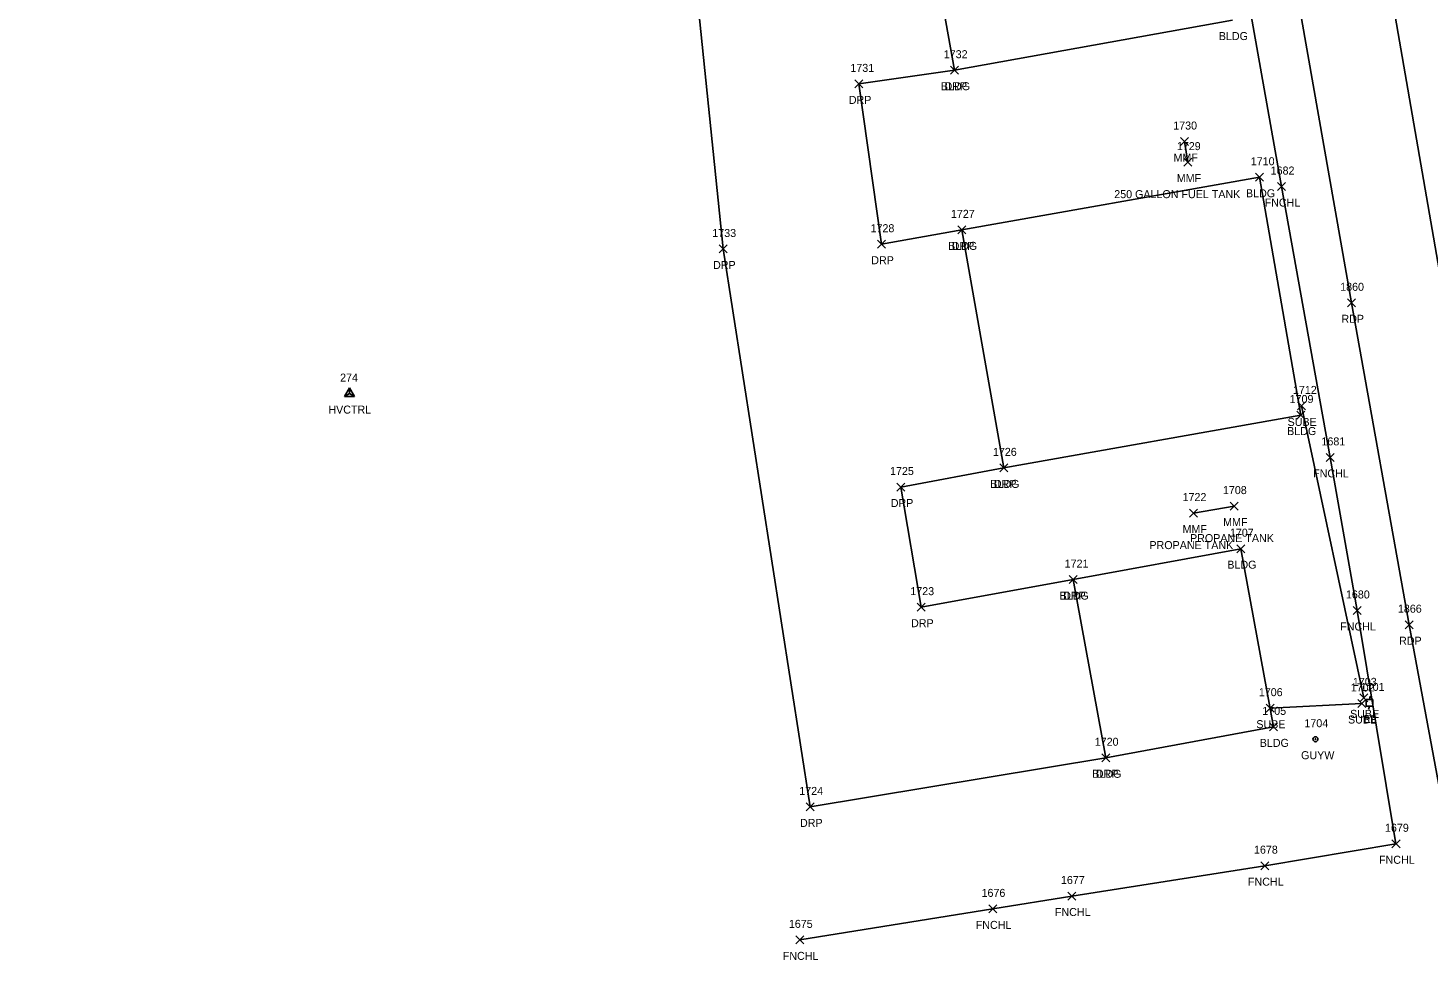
# Model space of a CAD drawing. Extents: x 1481523 to 1489083, y 884156 to 893756.
# Drawn here: x 1486301.2 to 1486651.1, y 888084.1 to 888317 of the extents above; entities that cross this region are included whole.
import ezdxf

# ---------------------------------------------------------------- set-up
doc = ezdxf.new("R2010")
doc.units = 0
for name, color, linetype in [('C_A', 7, 'Continuous'), ('C_I', 7, 'Continuous'), ('CPSM', 7, 'Continuous'), ('L_A', 7, 'Continuous'), ('L_C', 7, 'Continuous'), ('L_I', 7, 'Continuous'), ('L_TIC', 7, 'Continuous'), ('LBC', 7, 'Continuous'), ('LDEFAULT', 7, 'Continuous'), ('LFNC', 7, 'Continuous'), ('P_A', 7, 'Continuous'), ('P_I', 7, 'Continuous'), ('P_TIC', 7, 'Continuous'), ('PET', 7, 'Continuous'), ('R_A', 7, 'Continuous'), ('R_I', 7, 'Continuous'), ('R_TIC', 7, 'Continuous'), ('RDP', 7, 'Continuous'), ('U_A', 7, 'Continuous'), ('U_I', 7, 'Continuous'), ('U_TIC', 7, 'Continuous'), ('UE', 7, 'Continuous'), ('UEPT', 7, 'Continuous'), ('UPGW', 7, 'Continuous')]:
    doc.layers.add(name, color=color, linetype=linetype)

msp = doc.modelspace()

# ---------------------------------------------------------------- linework, layer by layer
at = {"layer": 'CPSM'}
for p, q in [((1486380.33, 888224.92), (1486381.58, 888227.08)), ((1486382.83, 888224.92), (1486381.58, 888227.08)), ((1486381.58, 888225.64), (1486381.58, 888227.08)), ((1486380.33, 888224.92), (1486381.58, 888225.64)), ((1486380.33, 888224.92), (1486382.83, 888224.92)), ((1486381.58, 888225.64), (1486381.58, 888225.64)), ((1486381.58, 888225.64), (1486382.83, 888224.92))]:
    msp.add_line(p, q, dxfattribs=at)
at = {"layer": 'L_TIC'}
for points in [[(1486531.76, 888305.44), (1486533.76, 888307.44)], [(1486533.76, 888305.44), (1486531.76, 888307.44)], [(1486589.19, 888287.61), (1486591.19, 888289.61)], [(1486591.19, 888287.61), (1486589.19, 888289.61)], [(1486590.02, 888282.47), (1486592.02, 888284.47)], [(1486592.02, 888282.47), (1486590.02, 888284.47)], [(1486608, 888278.69), (1486610, 888280.69)], [(1486610, 888278.69), (1486608, 888280.69)], [(1486613.5, 888276.37), (1486615.5, 888278.37)], [(1486615.5, 888276.37), (1486613.5, 888278.37)], [(1486533.55, 888265.55), (1486535.55, 888267.55)], [(1486535.55, 888265.55), (1486533.55, 888267.55)], [(1486533.55, 888265.55), (1486535.55, 888267.55)], [(1486535.55, 888265.55), (1486533.55, 888267.55)], [(1486618.28, 888219.28), (1486620.28, 888221.28)], [(1486620.28, 888219.28), (1486618.28, 888221.28)], [(1486618.28, 888219.28), (1486620.28, 888221.28)], [(1486620.28, 888219.28), (1486618.28, 888221.28)], [(1486625.62, 888208.7), (1486627.62, 888210.7)], [(1486627.62, 888208.7), (1486625.62, 888210.7)], [(1486544.1, 888206.08), (1486546.1, 888208.08)], [(1486546.1, 888206.08), (1486544.1, 888208.08)], [(1486601.6, 888196.53), (1486603.6, 888198.53)], [(1486603.6, 888196.53), (1486601.6, 888198.53)], [(1486591.45, 888194.79), (1486593.45, 888196.79)], [(1486593.45, 888194.79), (1486591.45, 888196.79)], [(1486603.34, 888185.89), (1486605.34, 888187.89)], [(1486605.34, 888185.89), (1486603.34, 888187.89)], [(1486561.41, 888178.16), (1486563.41, 888180.16)], [(1486563.41, 888178.16), (1486561.41, 888180.16)], [(1486561.41, 888178.16), (1486563.41, 888180.16)], [(1486563.41, 888178.16), (1486561.41, 888180.16)], [(1486632.4, 888170.45), (1486634.4, 888172.45)], [(1486634.4, 888170.45), (1486632.4, 888172.45)], [(1486611.44, 888141.37), (1486613.44, 888143.37)], [(1486613.44, 888141.37), (1486611.44, 888143.37)], [(1486611.44, 888141.37), (1486613.44, 888143.37)], [(1486613.44, 888141.37), (1486611.44, 888143.37)], [(1486569.58, 888133.65), (1486571.58, 888135.65)], [(1486571.58, 888133.65), (1486569.58, 888135.65)], [(1486642.08, 888112.16), (1486644.08, 888114.16)], [(1486644.08, 888112.16), (1486642.08, 888114.16)], [(1486609.33, 888106.69), (1486611.33, 888108.69)], [(1486611.33, 888106.69), (1486609.33, 888108.69)], [(1486561.09, 888099.11), (1486563.09, 888101.11)], [(1486563.09, 888099.11), (1486561.09, 888101.11)], [(1486541.31, 888095.89), (1486543.31, 888097.89)], [(1486543.31, 888095.89), (1486541.31, 888097.89)], [(1486493.1, 888088.15), (1486495.1, 888090.15)], [(1486495.1, 888088.15), (1486493.1, 888090.15)]]:
    msp.add_lwpolyline(points, dxfattribs=at)
at = {"layer": 'LBC'}
for points in [[(1486602.21, 888318.97), (1486532.76, 888306.44), (1486523.87, 888356.26)], [(1486619.28, 888220.28), (1486609, 888279.69), (1486534.55, 888266.55)], [(1486619.28, 888220.28), (1486545.1, 888207.08), (1486534.55, 888266.55)], [(1486612.44, 888142.37), (1486604.34, 888186.89), (1486562.41, 888179.16)], [(1486612.44, 888142.37), (1486570.58, 888134.65), (1486562.41, 888179.16)]]:
    msp.add_lwpolyline(points, dxfattribs=at)
at = {"layer": 'LDEFAULT'}
for points in [[(1486591.02, 888283.47), (1486590.19, 888288.61)], [(1486602.6, 888197.53), (1486592.45, 888195.79)]]:
    msp.add_lwpolyline(points, dxfattribs=at)
at = {"layer": 'LFNC'}
msp.add_lwpolyline([(1486494.1, 888089.15), (1486542.31, 888096.89), (1486562.09, 888100.11), (1486610.33, 888107.69), (1486643.08, 888113.16), (1486633.4, 888171.45), (1486626.62, 888209.7), (1486614.5, 888277.37), (1486602.35, 888345.54), (1486591.72, 888405.11), (1486588.69, 888421.87), (1486578, 888481.54), (1486565.98, 888549.48), (1486554.04, 888616.26), (1486540.66, 888690.96), (1486537.54, 888707.46), (1486527.52, 888764.64), (1486517.54, 888822.03), (1486505.67, 888889.2), (1486493.41, 888956.36), (1486481.11, 889023.64), (1486470.56, 889080.63), (1486461.7, 889127.71), (1486454.26, 889166.3)], dxfattribs=at)
at = {"layer": 'P_TIC'}
for points in [[(1486630.96, 888247.32), (1486632.96, 888249.32)], [(1486632.96, 888247.32), (1486630.96, 888249.32)], [(1486645.36, 888166.9), (1486647.36, 888168.9)], [(1486647.36, 888166.9), (1486645.36, 888168.9)]]:
    msp.add_lwpolyline(points, dxfattribs=at)
at = {"layer": 'PET'}
for points in [[(1486482.46, 889213.8), (1486493.22, 889156.8), (1486512.17, 889057.76), (1486527.58, 888974.51), (1486542.53, 888889.08), (1486553.79, 888825.37), (1486565.07, 888760.91), (1486577.19, 888690.78), (1486591.4, 888610.57), (1486602.78, 888547.25), (1486614.23, 888481.5), (1486627.06, 888409.28), (1486638.94, 888342.58), (1486654.61, 888252.22), (1486669.1, 888181.27), (1486680.17, 888112.03), (1486680.99, 888105.73)], [(1486459.06, 889211.36), (1486470.75, 889147.47), (1486504.42, 888970.47), (1486519.24, 888886.05), (1486530.77, 888821.38), (1486542.03, 888758.69), (1486549.22, 888711.97), (1486553.24, 888690.65), (1486568.55, 888607.7), (1486579.98, 888541.46), (1486590.64, 888481.54), (1486600.71, 888424.31), (1486604.32, 888404.42), (1486616.77, 888334.61), (1486631.96, 888248.32), (1486646.36, 888167.9), (1486656.21, 888114.83)]]:
    msp.add_lwpolyline(points, dxfattribs=at)
at = {"layer": 'R_TIC'}
for points in [[(1486531.76, 888305.44), (1486533.76, 888307.44)], [(1486533.76, 888305.44), (1486531.76, 888307.44)], [(1486507.85, 888302.02), (1486509.85, 888304.02)], [(1486509.85, 888302.02), (1486507.85, 888304.02)], [(1486533.55, 888265.55), (1486535.55, 888267.55)], [(1486535.55, 888265.55), (1486533.55, 888267.55)], [(1486473.92, 888260.77), (1486475.92, 888262.77)], [(1486475.92, 888260.77), (1486473.92, 888262.77)], [(1486513.47, 888261.96), (1486515.47, 888263.96)], [(1486515.47, 888261.96), (1486513.47, 888263.96)], [(1486544.1, 888206.08), (1486546.1, 888208.08)], [(1486546.1, 888206.08), (1486544.1, 888208.08)], [(1486518.34, 888201.3), (1486520.34, 888203.3)], [(1486520.34, 888201.3), (1486518.34, 888203.3)], [(1486561.41, 888178.16), (1486563.41, 888180.16)], [(1486563.41, 888178.16), (1486561.41, 888180.16)], [(1486523.4, 888171.28), (1486525.4, 888173.28)], [(1486525.4, 888171.28), (1486523.4, 888173.28)], [(1486569.58, 888133.65), (1486571.58, 888135.65)], [(1486571.58, 888133.65), (1486569.58, 888135.65)], [(1486495.65, 888121.37), (1486497.65, 888123.37)], [(1486497.65, 888121.37), (1486495.65, 888123.37)]]:
    msp.add_lwpolyline(points, dxfattribs=at)
at = {"layer": 'RDP'}
for points in [[(1486570.58, 888134.65), (1486496.65, 888122.37), (1486474.92, 888261.77), (1486467.85, 888330.77), (1486458.78, 888418.3), (1486415.84, 888670.58), (1486400.74, 888672.5), (1486301.22, 888657.33)], [(1486534.55, 888266.55), (1486514.47, 888262.96), (1486508.85, 888303.02), (1486532.76, 888306.44)], [(1486562.41, 888179.16), (1486524.4, 888172.28), (1486519.34, 888202.3), (1486545.1, 888207.08)]]:
    msp.add_lwpolyline(points, dxfattribs=at)
at = {"layer": 'U_TIC'}
for points in [[(1486618.46, 888221.56), (1486620.46, 888223.56)], [(1486620.46, 888221.56), (1486618.46, 888223.56)], [(1486633.54, 888147.21), (1486635.54, 888149.21)], [(1486635.54, 888147.21), (1486633.54, 888149.21)], [(1486634.07, 888148.62), (1486636.07, 888150.62)], [(1486636.07, 888148.62), (1486634.07, 888150.62)], [(1486610.63, 888146.04), (1486612.63, 888148.04)], [(1486612.63, 888146.04), (1486610.63, 888148.04)]]:
    msp.add_lwpolyline(points, dxfattribs=at)
at = {"layer": 'UE'}
for points in [[(1486635.07, 888149.62), (1486619.46, 888222.56)], [(1486634.54, 888148.21), (1486611.63, 888147.04)]]:
    msp.add_lwpolyline(points, dxfattribs=at)
at = {"layer": 'UEPT'}
for p, q in [((1486635.64, 888147.53), (1486635.64, 888149.19)), ((1486635.64, 888149.19), (1486637.31, 888149.19)), ((1486636.64, 888150.03), (1486636.47, 888149.19)), ((1486637.31, 888149.19), (1486637.31, 888147.53)), ((1486637.31, 888147.53), (1486635.64, 888147.53)), ((1486636.22, 888146.69), (1486636.47, 888147.53)), ((1486636.47, 888148.36), (1486636.47, 888148.36))]:
    msp.add_line(p, q, dxfattribs=at)
at = {"layer": 'UPGW'}
for radius in [0.625, 0.0833]:
    msp.add_circle((1486622.96, 888139.29), radius, dxfattribs=at)

# ---------------------------------------------------------------- texts
at = {"layer": 'C_A'}
msp.add_text('HVCTRL', height=2, dxfattribs=at).set_placement((1486376.28, 888220.64))
at = {"layer": 'C_I'}
msp.add_text('274', height=2, dxfattribs=at).set_placement((1486379.22, 888228.64))
at = {"layer": 'L_A'}
for s, p in [('BLDG', (1486598.8, 888313.97)), ('BLDG', (1486598.8, 888313.97)), ('BLDG', (1486529.35, 888301.44)), ('MMF', (1486587.48, 888283.61)), ('MMF', (1486588.3, 888278.47)), ('BLDG', (1486605.59, 888274.69)), ('FNCHL', (1486610.25, 888272.37)), ('BLDG', (1486531.14, 888261.55)), ('BLDG', (1486531.14, 888261.55)), ('BLDG', (1486615.87, 888215.28)), ('BLDG', (1486615.87, 888215.28)), ('FNCHL', (1486622.37, 888204.7)), ('BLDG', (1486541.69, 888202.08)), ('MMF', (1486599.88, 888192.53)), ('MMF', (1486589.73, 888190.79)), ('BLDG', (1486600.93, 888181.89)), ('BLDG', (1486559, 888174.16)), ('BLDG', (1486559, 888174.16)), ('FNCHL', (1486629.14, 888166.45)), ('BLDG', (1486609.03, 888137.37)), ('BLDG', (1486609.03, 888137.37)), ('BLDG', (1486567.17, 888129.65)), ('FNCHL', (1486638.83, 888108.16)), ('FNCHL', (1486606.08, 888102.69)), ('FNCHL', (1486557.84, 888095.11)), ('FNCHL', (1486538.06, 888091.89)), ('FNCHL', (1486489.85, 888084.15))]:
    msp.add_text(s, height=2, dxfattribs=at).set_placement(p)
at = {"layer": 'L_C'}
for s, p in [('250 GALLON FUEL TANK', (1486572.67, 888274.47)), ('PROPANE TANK', (1486581.46, 888186.79)), ('PROPANE TANK', (1486591.61, 888188.53))]:
    msp.add_text(s, height=2, dxfattribs=at).set_placement(p)
at = {"layer": 'L_I'}
for s, p in [('1732', (1486530.07, 888309.44)), ('1730', (1486587.41, 888291.61)), ('1729', (1486588.32, 888286.47)), ('1710', (1486606.79, 888282.69)), ('1682', (1486611.76, 888280.37)), ('1727', (1486531.86, 888269.55)), ('1727', (1486531.86, 888269.55)), ('1709', (1486616.5, 888223.28)), ('1709', (1486616.5, 888223.28)), ('1726', (1486542.35, 888210.08)), ('1681', (1486624.45, 888212.7)), ('1708', (1486599.83, 888200.53)), ('1722', (1486589.75, 888198.79)), ('1707', (1486601.57, 888189.89)), ('1721', (1486560.28, 888182.16)), ('1721', (1486560.28, 888182.16)), ('1680', (1486630.57, 888174.45)), ('1705', (1486609.67, 888145.37)), ('1705', (1486609.67, 888145.37)), ('1720', (1486567.8, 888137.65)), ('1679', (1486640.33, 888116.16)), ('1678', (1486607.59, 888110.69)), ('1677', (1486559.35, 888103.11)), ('1676', (1486539.51, 888099.89)), ('1675', (1486491.36, 888092.15))]:
    msp.add_text(s, height=2, dxfattribs=at).set_placement(p)
at = {"layer": 'P_A'}
for p in [(1486629.45, 888243.32), (1486643.85, 888162.9)]:
    msp.add_text('RDP', height=2, dxfattribs=at).set_placement(p)
at = {"layer": 'P_I'}
for s, p in [('1860', (1486629.13, 888251.32)), ('1866', (1486643.56, 888170.9))]:
    msp.add_text(s, height=2, dxfattribs=at).set_placement(p)
at = {"layer": 'R_A'}
for p in [(1486530.25, 888301.44), (1486506.34, 888298.02), (1486532.04, 888261.55), (1486472.41, 888256.77), (1486511.95, 888257.96), (1486542.59, 888202.08), (1486516.82, 888197.3), (1486559.9, 888174.16), (1486521.89, 888167.28), (1486568.07, 888129.65), (1486494.14, 888117.37)]:
    msp.add_text('DRP', height=2, dxfattribs=at).set_placement(p)
at = {"layer": 'R_I'}
for s, p in [('1732', (1486530.07, 888309.44)), ('1731', (1486506.73, 888306.02)), ('1727', (1486531.86, 888269.55)), ('1728', (1486511.77, 888265.96)), ('1733', (1486472.23, 888264.77)), ('1726', (1486542.35, 888210.08)), ('1725', (1486516.64, 888205.3)), ('1721', (1486560.28, 888182.16)), ('1723', (1486521.71, 888175.28)), ('1720', (1486567.8, 888137.65)), ('1724', (1486493.96, 888125.37))]:
    msp.add_text(s, height=2, dxfattribs=at).set_placement(p)
at = {"layer": 'U_A'}
for s, p in [('SUBE', (1486615.99, 888217.56)), ('SUBE', (1486631.6, 888144.62)), ('SUBE', (1486608.17, 888142.04)), ('SUBE', (1486631.08, 888143.21)), ('EL', (1486635.01, 888143.36)), ('GUYW', (1486619.36, 888134.29))]:
    msp.add_text(s, height=2, dxfattribs=at).set_placement(p)
at = {"layer": 'U_I'}
for s, p in [('1712', (1486617.33, 888225.56)), ('1702', (1486631.77, 888151.21)), ('1703', (1486632.3, 888152.62)), ('1701', (1486634.27, 888151.36)), ('1706', (1486608.8, 888150.04)), ('1704', (1486620.19, 888142.29))]:
    msp.add_text(s, height=2, dxfattribs=at).set_placement(p)

doc.saveas('drawing.dxf')
